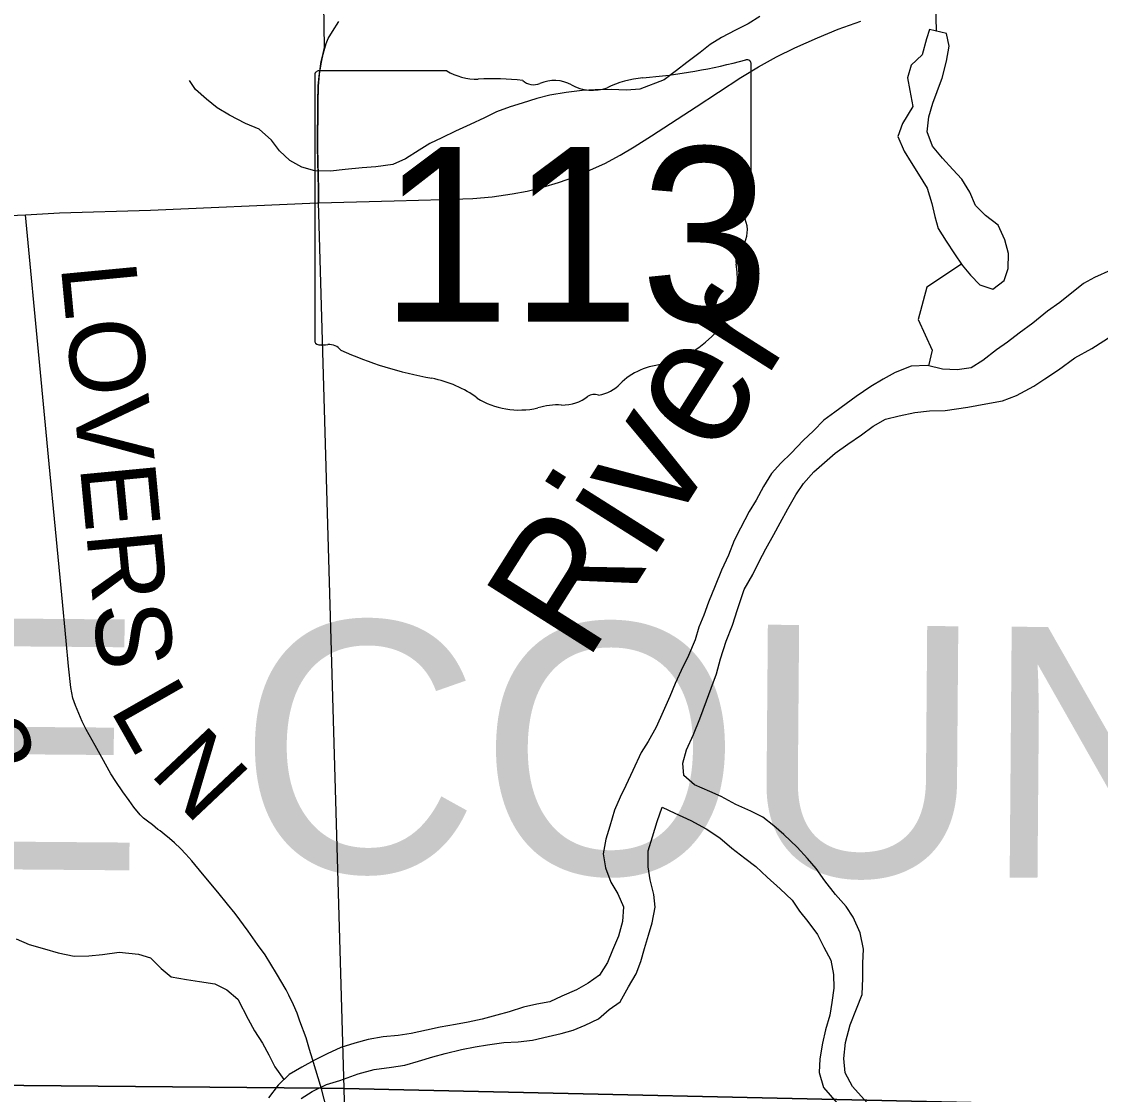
# Model space of a CAD drawing. Extents: x 0 to 34, y 0 to 22.
# Drawn here: x 22.573 to 23.388, y 15.383 to 16.194 of the extents above; entities that cross this region are included whole.
import ezdxf

# ---------------------------------------------------------------- set-up
doc = ezdxf.new("R2010")
doc.units = 0
for name, color, linetype in [('GM_X_County_Road', 7, 'Continuous'), ('GM_X_County_Text', 7, 'Continuous'), ('GM_X_Major_River', 7, 'Continuous'), ('GM_X_Major_River_Text', 7, 'Continuous'), ('GM_X_Minor_Lake', 7, 'Continuous'), ('GM_X_Minor_River', 7, 'Continuous'), ('GM_X_Rail_Line', 7, 'Continuous'), ('GM_X_State_Location', 7, 'Continuous'), ('GM_X_State_Route', 7, 'Continuous'), ('GM_X_State_Shield', 7, 'Continuous'), ('GM_X_Township_Road', 7, 'Continuous'), ('GM_X_Township_Road_Text', 7, 'Continuous'), ('SH_Cut_Line', 7, 'Continuous')]:
    doc.layers.add(name, color=color, linetype=linetype)

msp = doc.modelspace()

# ---------------------------------------------------------------- linework, layer by layer
at = {"layer": 'GM_X_County_Road'}
msp.add_lwpolyline([(22.81893, 15.12169), (22.79487, 15.14783), (22.78423, 15.16221), (22.77891, 15.17131), (22.77624, 15.17851), (22.7747, 15.18724), (22.77079, 15.23315), (22.77152, 15.24416), (22.77528, 15.25139), (22.78548, 15.25939), (22.80551, 15.27273), (22.81381, 15.28301), (22.81771, 15.29034), (22.81922, 15.30799), (22.81577, 15.32628), (22.79991, 15.38755)], dxfattribs=at)
at = {"layer": 'GM_X_Major_River'}
for points in [[(23.39593, 16.00585), (23.38373, 16.00027), (23.37534, 15.9958), (23.35736, 15.98154), (23.34819, 15.9748), (23.33709, 15.96579), (23.32677, 15.95829), (23.31797, 15.95154), (23.30957, 15.94555), (23.29924, 15.93768), (23.29046, 15.93207), (23.27982, 15.93065), (23.26881, 15.93115), (23.25745, 15.93392), (23.2453, 15.93329), (23.2331, 15.92847), (23.22395, 15.92363), (23.21478, 15.91802), (23.2037, 15.91053), (23.19606, 15.90491), (23.18764, 15.89854), (23.17924, 15.89254), (23.17157, 15.88464), (23.16353, 15.87712), (23.15471, 15.86771), (23.14666, 15.86019), (23.13975, 15.85229), (23.13359, 15.84247), (23.12817, 15.83226), (23.12278, 15.82358), (23.11621, 15.8111), (23.11156, 15.80165), (23.10728, 15.79067), (23.10186, 15.77933), (23.09719, 15.76759), (23.09214, 15.7551), (23.08863, 15.74526), (23.08474, 15.73618), (23.082, 15.7267), (23.07695, 15.71497), (23.07153, 15.70363), (23.06688, 15.69379), (23.06299, 15.68395), (23.05795, 15.6726), (23.05252, 15.66088), (23.04672, 15.64992), (23.04133, 15.64161), (23.03513, 15.62799), (23.0297, 15.61665), (23.02545, 15.60795), (23.02117, 15.59811), (23.01764, 15.58598), (23.01451, 15.57614), (23.01251, 15.56514), (23.01431, 15.55447), (23.01838, 15.54379), (23.02361, 15.535), (23.02807, 15.52507), (23.02721, 15.51406), (23.02407, 15.50307), (23.01979, 15.49247), (23.0159, 15.48301), (23.00974, 15.47357), (23.00133, 15.46758), (22.99255, 15.46235), (22.9815, 15.45752), (22.97235, 15.45343), (22.96246, 15.45163), (22.95257, 15.44946), (22.94153, 15.44577), (22.93239, 15.4432), (22.92136, 15.44027), (22.91071, 15.4381), (22.9012, 15.4363), (22.88941, 15.43414), (22.87914, 15.43197), (22.86773, 15.42942), (22.85785, 15.42801), (22.84645, 15.42698), (22.83504, 15.42482), (22.82514, 15.42226), (22.81448, 15.41895), (22.80419, 15.41411), (22.79465, 15.40927), (22.78511, 15.40405), (22.77557, 15.39845), (22.76714, 15.39055), (22.75987, 15.38088)], [(23.21197, 15.37702), (23.20102, 15.38951), (23.19543, 15.39983), (23.19439, 15.41049), (23.19564, 15.42263), (23.19919, 15.4359), (23.20386, 15.44801), (23.20814, 15.45899), (23.20863, 15.47115), (23.20874, 15.48255), (23.20922, 15.49319), (23.20668, 15.50537), (23.20148, 15.51721), (23.19624, 15.52524), (23.18798, 15.53445), (23.1801, 15.54479), (23.17336, 15.55398), (23.16698, 15.56165), (23.15909, 15.57009), (23.14893, 15.57969), (23.1414, 15.58623), (23.13311, 15.59278), (23.12404, 15.59743), (23.1127, 15.60249), (23.10175, 15.6083), (23.09306, 15.61219), (23.08171, 15.61725), (23.07343, 15.62418), (23.07276, 15.63369), (23.07551, 15.64354), (23.08094, 15.65526), (23.0856, 15.667), (23.09067, 15.68063), (23.09417, 15.69009), (23.09808, 15.70107), (23.10122, 15.71244), (23.10552, 15.7257), (23.11019, 15.73781), (23.1141, 15.74955), (23.11918, 15.76471), (23.12574, 15.77604), (23.13039, 15.78587), (23.13542, 15.79532), (23.14159, 15.80628), (23.14623, 15.81497), (23.15203, 15.82555), (23.1582, 15.83613), (23.16398, 15.84481), (23.17165, 15.85348), (23.18773, 15.86775), (23.19729, 15.8745), (23.2076, 15.88161), (23.21639, 15.88798), (23.22593, 15.8932), (23.23621, 15.89576), (23.248, 15.8983), (23.25902, 15.8997), (23.27079, 15.89996), (23.2879, 15.90245), (23.30159, 15.90497), (23.31414, 15.90712), (23.3248, 15.91119), (23.33778, 15.91828), (23.34618, 15.92389), (23.35649, 15.93062), (23.36873, 15.93962), (23.3817, 15.94671), (23.39698, 15.95643)], [(22.78453, 15.38033), (22.79291, 15.38573), (22.80359, 15.39094), (22.81387, 15.39387), (22.82758, 15.39905), (22.83976, 15.40235), (22.85268, 15.40412), (22.86295, 15.40553), (22.87322, 15.40847), (22.88388, 15.41178), (22.8934, 15.41434), (22.90557, 15.41725), (22.91584, 15.41943), (22.92535, 15.42085), (22.93751, 15.42263), (22.94853, 15.42327), (22.95917, 15.4243), (22.97096, 15.42722), (22.98085, 15.4294), (22.98999, 15.43197), (22.99913, 15.43568), (23.00905, 15.44051), (23.01709, 15.44765), (23.02549, 15.45327), (23.03167, 15.4646), (23.03746, 15.47443), (23.04097, 15.48389), (23.04372, 15.49375), (23.04685, 15.50359), (23.0496, 15.51307), (23.05199, 15.52482), (23.05094, 15.53434), (23.04801, 15.54539), (23.04658, 15.55529), (23.0467, 15.56744), (23.04983, 15.57805), (23.05336, 15.58942), (23.05726, 15.6004), (23.06671, 15.59574), (23.0788, 15.5903), (23.09051, 15.5841), (23.10069, 15.57715), (23.10973, 15.56946), (23.11953, 15.56176), (23.12782, 15.55559), (23.13647, 15.54752), (23.14626, 15.53868), (23.15529, 15.53022), (23.1609, 15.5218), (23.16728, 15.51414), (23.1744, 15.50418), (23.17925, 15.49463), (23.18447, 15.4847), (23.18664, 15.47403), (23.18692, 15.46377), (23.1853, 15.45276), (23.18369, 15.44328), (23.18055, 15.43229), (23.17818, 15.42205), (23.17617, 15.41029), (23.17569, 15.40004), (23.179, 15.3886), (23.189, 15.37716)]]:
    msp.add_lwpolyline(points, dxfattribs=at)
at = {"layer": 'GM_X_Minor_Lake'}
for points in [[(23.25908, 16.18766), (23.25676, 16.18058), (23.25361, 16.16845), (23.24518, 16.16055), (23.24244, 16.15108), (23.24424, 16.14156), (23.24641, 16.12938), (23.23869, 16.11654), (23.23518, 16.10669), (23.24001, 16.09562), (23.24524, 16.08721), (23.25085, 16.07841), (23.25721, 16.0677), (23.26089, 16.05626), (23.26307, 16.04636), (23.26564, 16.03721), (23.27163, 16.02765), (23.27799, 16.01808), (23.2836, 16.00966), (23.28999, 16.002), (23.29713, 15.9947), (23.30697, 15.99156), (23.31538, 15.99794), (23.3185, 16.00702), (23.31861, 16.01843), (23.31605, 16.02871), (23.31084, 16.03979), (23.30142, 16.0471), (23.2939, 16.05478), (23.28944, 16.06471), (23.28346, 16.07465), (23.2767, 16.08194), (23.26881, 16.09038), (23.2613, 16.09958), (23.25723, 16.11026), (23.25848, 16.12165), (23.26161, 16.13188), (23.26814, 16.14958)], [(23.26814, 16.14958), (23.26863, 16.15081), (23.27179, 16.1637), (23.27379, 16.17508), (23.27198, 16.1846), (23.25908, 16.18766)]]:
    msp.add_lwpolyline(points, dxfattribs=at)
at = {"layer": 'GM_X_Minor_River'}
for points in [[(23.25494, 16.24061), (23.25871, 16.22578), (23.26319, 16.21737), (23.26346, 16.20635), (23.264, 16.1865)], [(23.13089, 16.19745), (23.12211, 16.19184), (23.11257, 16.187), (23.10189, 16.18141), (23.09349, 16.17617), (23.08584, 16.17017), (23.0759, 16.16267), (23.06787, 16.15668), (23.05869, 16.14955), (23.0404, 16.14252), (23.03015, 16.14186), (23.01876, 16.14236), (23.00661, 16.1421), (22.99674, 16.14144), (22.98457, 16.14005), (22.97241, 16.13789), (22.96251, 16.13533), (22.95147, 16.13203), (22.94234, 16.12908), (22.93205, 16.12539), (22.9229, 16.12092), (22.91222, 16.11571), (22.90116, 16.11088), (22.89086, 16.10567), (22.88172, 16.10158), (22.87369, 16.09634), (22.86338, 16.08999), (22.85385, 16.08553), (22.84093, 16.08376), (22.83067, 16.08311), (22.81775, 16.08172), (22.80674, 16.08069), (22.79497, 16.08081), (22.78512, 16.08357), (22.77606, 16.08861), (22.76816, 16.09591), (22.76216, 16.10395), (22.75275, 16.11241), (22.74254, 16.11669), (22.73046, 16.1229), (22.72102, 16.12831), (22.71311, 16.13486), (22.70483, 16.14216), (22.70034, 16.14905)], [(23.28318, 16.01029), (23.25714, 15.99295), (23.25053, 15.96865), (23.26105, 15.94539), (23.25839, 15.93369)], [(22.56928, 15.5009), (22.57911, 15.49662), (22.59084, 15.49346), (22.60106, 15.49031), (22.61319, 15.48791), (22.6242, 15.48817), (22.63446, 15.48921), (22.647, 15.49098), (22.66179, 15.48931), (22.67088, 15.48655), (22.67877, 15.47849), (22.68631, 15.47233), (22.69805, 15.47031), (22.70791, 15.46869), (22.71928, 15.46706), (22.72835, 15.4624), (22.73663, 15.45547), (22.74446, 15.44019), (22.74931, 15.4314), (22.7553, 15.42222), (22.76015, 15.41343), (22.76462, 15.40426), (22.77157, 15.3947)]]:
    msp.add_lwpolyline(points, dxfattribs=at)
at = {"layer": 'GM_X_Rail_Line'}
for points in [[(21.7404, 20.42151), (21.7404, 15.39913), (21.84376, 15.39569), (22.15405, 15.39394), (22.79969, 15.38811), (22.81708, 15.3878), (22.79758, 16.0573), (22.79757, 16.06725), (22.79683, 16.0986), (22.79708, 16.13269), (22.79749, 16.14507), (22.79829, 16.15433), (22.7997, 16.16348), (22.80107, 16.16945), (22.8022, 16.174), (22.78887, 17.04474), (22.77639, 17.88363), (22.76822, 18.23412), (22.7679, 18.24823), (22.75894, 18.64947), (22.73442, 20.39832)], [(21.7404, 15.39913), (21.7404, 14.1), (22.8511, 14.1), (22.84358, 14.47408), (22.83864, 14.61592), (22.83423, 14.81058), (22.82389, 15.11203), (22.819, 15.30855), (22.81708, 15.3878), (22.79969, 15.38811), (22.15405, 15.39394), (21.84376, 15.39569)]]:
    msp.add_lwpolyline(points, close=True, dxfattribs=at)
at = {"layer": 'GM_X_State_Route'}
for points in [[(22.7978, 16.05675), (22.8547, 16.05821), (22.89155, 16.05917), (22.91409, 16.05993), (22.92879, 16.06108), (22.94387, 16.06337), (22.95533, 16.06547), (22.96717, 16.06853), (22.97901, 16.07196), (22.99123, 16.07635), (23.00307, 16.08151), (23.01395, 16.08629), (23.02541, 16.09278), (23.03592, 16.09898), (23.04915, 16.10716), (23.08287, 16.12927), (23.11662, 16.15143), (23.12989, 16.15944), (23.1435, 16.16682), (23.15741, 16.17365), (23.17439, 16.18121), (23.1902, 16.18789), (23.2072, 16.19381)], [(22.52281, 16.04539), (22.57628, 16.0475), (22.60206, 16.04903), (22.67079, 16.05125), (22.79701, 16.05671), (22.7978, 16.05675)]]:
    msp.add_lwpolyline(points, dxfattribs=at)
at = {"layer": 'GM_X_State_Shield'}
for p, q in [((22.89459, 16.15641), (22.79807, 16.15641)), ((23.12441, 16.05668), (23.12441, 16.16137)), ((22.79483, 16.15296), (22.79483, 15.95284)), ((23.12438, 16.05671), (23.12441, 16.05668))]:
    msp.add_line(p, q, dxfattribs=at)
for centre, major_axis, start_param, end_param in [((23.00701, 16.42924), (0.34952, 0), 4.814394, 5.042369), ((23.12075, 16.1618), (0.00367, 0), 6.141152, 7.989035), ((22.7986, 16.15339), (0.00382, 0), 1.712693, 3.28349), ((22.91758, 16.17964), (0.03703, 0), 4.042523, 4.731795), ((22.92986, 16.04406), (0.13295, 0), 1.404758, 1.657858), ((22.96004, 16.15443), (0.01068, 0), 3.836095, 5.185415), ((22.97572, 16.1313), (0.02221, 0), 0.950623, 2.079405), ((23.05159, 16.09528), (0.07032, 0), 1.699011, 2.107814), ((23.0044, 16.16302), (0.02672, 0), 4.081561, 5.145723), ((23.12356, 16.049), (0.00568, 0), 1.883978, 3.671073), ((23.12049, 16.05628), (0.00393, 0), 5.05454, 6.418171), ((23.08744, 16.03576), (0.03409, 0), 5.934695, 6.695948), ((23.13755, 16.01287), (0.0248, 0), 2.387724, 3.262537), ((23.02659, 15.99955), (0.08742, 0), 5.101752, 6.440018), ((22.79864, 15.95241), (0.00385, 0), 3.00124, 4.508301), ((22.79922, 15.97288), (0.0294, 0), 4.665946, 4.897461), ((22.80523, 15.9413), (0.0106, 0), 0.519207, 1.627899), ((22.93906, 16.1211), (0.2524, 0), 4.195997, 4.488961), ((23.06345, 15.89666), (0.04788, 0), 1.647645, 2.488434), ((22.86381, 15.86294), (0.07897, 0), 0.823519, 1.323587), ((23.00278, 15.93345), (0.02824, 0), 4.937069, 5.64225), ((23.00599, 15.90594), (0.00752, 0), 1.147584, 2.315152), ((22.94922, 15.94031), (0.05011, 0), 4.026481, 4.996735), ((22.97818, 15.87112), (0.04118, 0), 1.495662, 1.94098), ((22.98184, 15.92532), (0.0267, 0), 4.691044, 5.507374)]:
    msp.add_ellipse(centre, major_axis=major_axis, ratio=0.8, start_param=start_param, end_param=end_param, dxfattribs=at)
at = {"layer": 'GM_X_Township_Road'}
for points in [[(22.80242, 16.17344), (22.80354, 16.17706), (22.80505, 16.18077), (22.80811, 16.18593), (22.81309, 16.19359)], [(22.7978, 16.05675), (22.79779, 16.0667), (22.79705, 16.09805), (22.79729, 16.13214), (22.79771, 16.14452), (22.79851, 16.15378), (22.79992, 16.16292), (22.80129, 16.1689), (22.80242, 16.17344)], [(22.79088, 15.41736), (22.78825, 15.4262), (22.78366, 15.43882), (22.78155, 15.44476), (22.77888, 15.45107), (22.77524, 15.45834), (22.77313, 15.46255), (22.76588, 15.47476), (22.75731, 15.48876), (22.7517, 15.49661), (22.74462, 15.50675), (22.73467, 15.52017), (22.72891, 15.52719), (22.72165, 15.53622), (22.70999, 15.54999), (22.70194, 15.55994), (22.69755, 15.56491), (22.69334, 15.56912), (22.68893, 15.57333), (22.68514, 15.57658), (22.68109, 15.57984), (22.67802, 15.5826), (22.67625, 15.58358), (22.67229, 15.58692), (22.66846, 15.58978), (22.66559, 15.59208), (22.6631, 15.59457), (22.65832, 15.60031), (22.65468, 15.60529), (22.6499, 15.61198), (22.64454, 15.61983), (22.64091, 15.62557), (22.63402, 15.63781), (22.62904, 15.64699), (22.62233, 15.65902), (22.61928, 15.66498), (22.61665, 15.67112), (22.61411, 15.67704), (22.6122, 15.68259), (22.61067, 15.69081), (22.60894, 15.7067), (22.60709, 15.72605), (22.60375, 15.7607), (22.59901, 15.8102), (22.59418, 15.85969), (22.58711, 15.93396), (22.57628, 16.0475)], [(22.79991, 15.38755), (22.79304, 15.41012), (22.79088, 15.41736)]]:
    msp.add_lwpolyline(points, dxfattribs=at)
at = {"layer": 'SH_Cut_Line'}
for points in [[(21.7404, 20.9), (21.7404, 15.39913), (21.84376, 15.39569), (22.15405, 15.39394), (22.79969, 15.38811), (22.81708, 15.3878), (23.80935, 15.36588), (24.21343, 15.36582), (24.72905, 15.3682)], [(24.72905, 15.3682), (24.21343, 15.36582), (23.80935, 15.36588), (22.81708, 15.3878), (22.79969, 15.38811), (22.15405, 15.39394), (21.84376, 15.39569), (21.7404, 15.39913), (21.7404, 14.1), (28.5404, 14.1)]]:
    msp.add_lwpolyline(points, dxfattribs=at)

# ---------------------------------------------------------------- texts
at = {"layer": 'GM_X_County_Text'}
msp.add_text('ERIE COUNTY', height=0.1893939, rotation=359.53411, dxfattribs=at).set_placement((22.07457, 15.55735))
at = {"layer": 'GM_X_Major_River_Text'}
msp.add_text('River', height=0.094751, rotation=57.68778, dxfattribs=at).set_placement((22.99972, 15.70864))
at = {"layer": 'GM_X_State_Location'}
for s, p in [('s', (22.95592, 16.0396)), ('r', (22.95591, 16.0396))]:
    msp.add_text(s, height=0.000189, dxfattribs=at).set_placement(p)
msp.add_text('113', height=0.000189, rotation=0.00001, dxfattribs=at).set_placement((22.88906, 16.02582))
at = {"layer": 'GM_X_State_Shield'}
msp.add_text('113', height=0.131836, dxfattribs=at).set_placement((22.84429, 15.96696))
at = {"layer": 'GM_X_Township_Road_Text'}
for s, height, rotation, p in [('LOVERS', 0.056818, 275.43192, (22.603, 16.00915)), ('L', 0.05682, 299.6609, (22.63959, 15.6744)), ('8', 0.05682, 290.50279, (22.51791, 15.65539)), ('N', 0.05682, 313.30127, (22.66924, 15.62582))]:
    msp.add_text(s, height=height, rotation=rotation, dxfattribs=at).set_placement(p)

doc.saveas('drawing.dxf')
